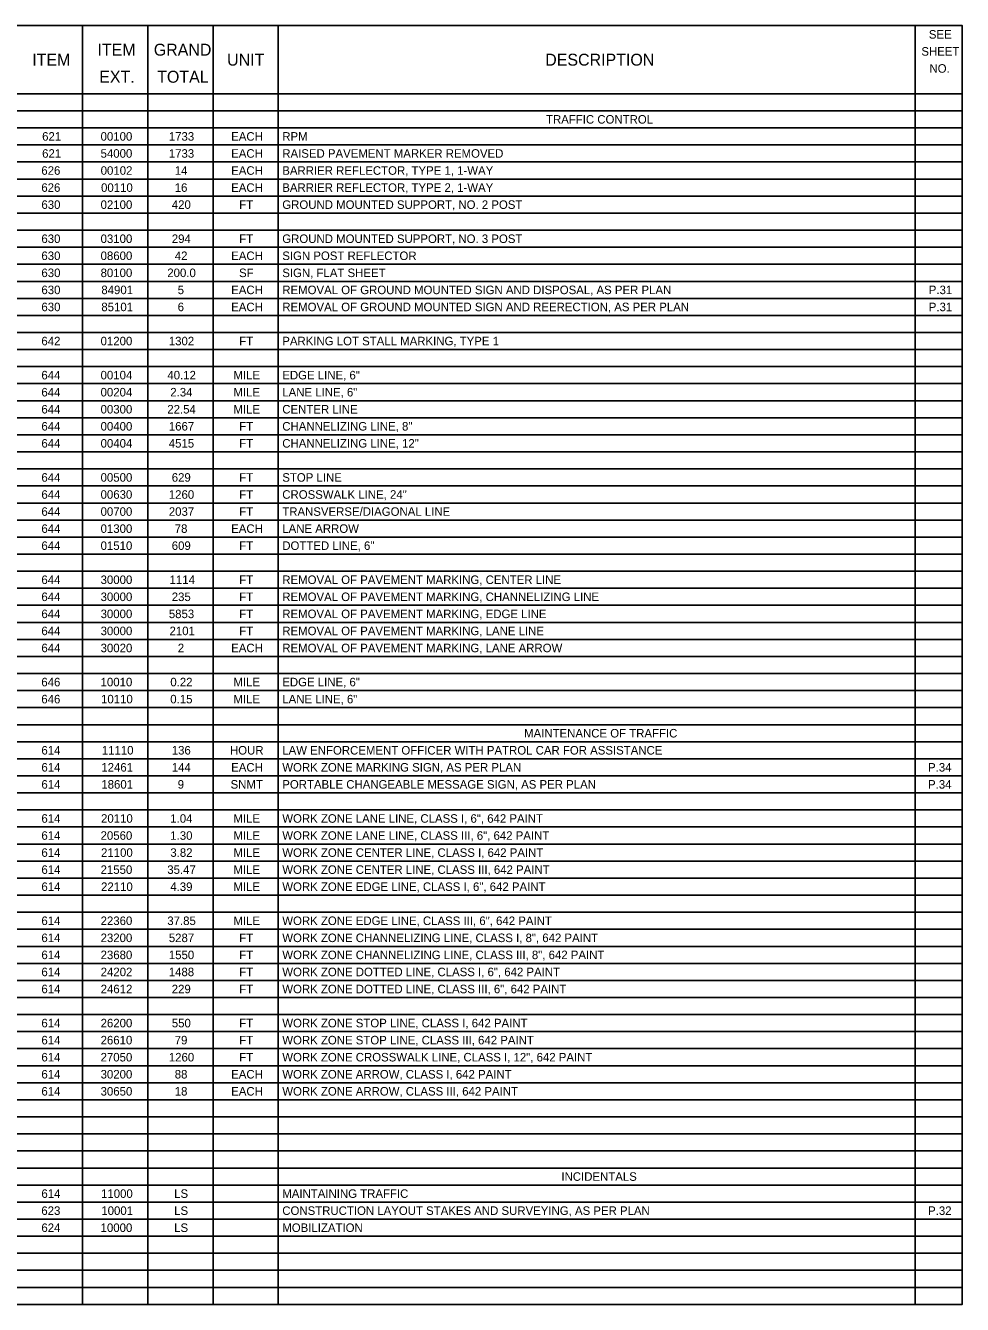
# Model space of a CAD drawing. Extents: x 12522 to 13018, y 1124 to 1902.
# Drawn here: x 12736.42 to 12751.8, y 1804.65 to 1825.65 of the extents above; entities that cross this region are included whole.
import ezdxf

# ---------------------------------------------------------------- set-up
doc = ezdxf.new("R2010")
doc.units = 0
for name, color, linetype in [('SC_Scratch1', 7, 'Continuous'), ('SH_Data', 7, 'Continuous'), ('SH_Text', 7, 'Continuous')]:
    doc.layers.add(name, color=color, linetype=linetype)

msp = doc.modelspace()

# ---------------------------------------------------------------- linework, layer by layer
at = {"layer": 'SC_Scratch1'}
msp.add_lwpolyline([(12721.301, 1825.65), (12751.801, 1825.65), (12751.801, 1804.65), (12721.301, 1804.65)], close=True, dxfattribs=at)
at = {"layer": 'SH_Data'}
for p, q in [((12737.359, 1825.65), (12737.359, 1804.65)), ((12738.43, 1825.65), (12738.43, 1804.65)), ((12739.501, 1825.65), (12739.501, 1804.65)), ((12740.571, 1825.65), (12740.571, 1804.65)), ((12751.03, 1825.65), (12751.03, 1804.65)), ((12721.301, 1824.53), (12751.804, 1824.53)), ((12721.301, 1824.25), (12751.804, 1824.25)), ((12721.301, 1823.97), (12751.804, 1823.97)), ((12721.301, 1823.69), (12751.804, 1823.69)), ((12721.301, 1823.41), (12751.804, 1823.41)), ((12721.301, 1823.13), (12751.804, 1823.13)), ((12721.301, 1822.85), (12751.804, 1822.85)), ((12721.301, 1822.57), (12751.804, 1822.57)), ((12721.301, 1822.29), (12751.804, 1822.29)), ((12721.301, 1822.01), (12751.804, 1822.01)), ((12721.301, 1821.73), (12751.804, 1821.73)), ((12721.301, 1821.45), (12751.804, 1821.45)), ((12721.301, 1821.17), (12751.804, 1821.17)), ((12721.301, 1820.89), (12751.804, 1820.89)), ((12721.301, 1820.61), (12751.804, 1820.61)), ((12721.301, 1820.33), (12751.804, 1820.33)), ((12721.301, 1820.05), (12751.804, 1820.05)), ((12721.301, 1819.77), (12751.804, 1819.77)), ((12721.301, 1819.49), (12751.804, 1819.49)), ((12721.301, 1819.21), (12751.804, 1819.21)), ((12721.301, 1818.93), (12751.804, 1818.93)), ((12721.301, 1818.65), (12751.804, 1818.65)), ((12721.301, 1818.37), (12751.804, 1818.37)), ((12721.301, 1818.09), (12751.804, 1818.09)), ((12721.301, 1817.81), (12751.804, 1817.81)), ((12721.301, 1817.53), (12751.804, 1817.53)), ((12721.301, 1817.25), (12751.804, 1817.25)), ((12721.301, 1816.97), (12751.804, 1816.97)), ((12721.301, 1816.69), (12751.804, 1816.69)), ((12721.301, 1816.41), (12751.804, 1816.41)), ((12721.301, 1816.13), (12751.804, 1816.13)), ((12721.301, 1815.85), (12751.804, 1815.85)), ((12721.301, 1815.57), (12751.804, 1815.57)), ((12721.301, 1815.29), (12751.804, 1815.29)), ((12721.301, 1815.01), (12751.804, 1815.01)), ((12721.301, 1814.73), (12751.804, 1814.73)), ((12721.301, 1814.45), (12751.804, 1814.45)), ((12721.301, 1814.17), (12751.804, 1814.17)), ((12721.301, 1813.89), (12751.804, 1813.89)), ((12721.301, 1813.61), (12751.804, 1813.61)), ((12721.301, 1813.33), (12751.804, 1813.33)), ((12721.301, 1813.05), (12751.804, 1813.05)), ((12721.301, 1812.77), (12751.804, 1812.77)), ((12721.301, 1812.49), (12751.804, 1812.49)), ((12721.301, 1812.21), (12751.804, 1812.21)), ((12721.301, 1811.93), (12751.804, 1811.93)), ((12721.301, 1811.65), (12751.804, 1811.65)), ((12721.301, 1811.37), (12751.804, 1811.37)), ((12721.301, 1811.09), (12751.804, 1811.09)), ((12721.301, 1810.81), (12751.804, 1810.81)), ((12721.301, 1810.53), (12751.804, 1810.53)), ((12721.301, 1810.25), (12751.804, 1810.25)), ((12721.301, 1809.97), (12751.804, 1809.97)), ((12721.301, 1809.69), (12751.804, 1809.69)), ((12721.301, 1809.41), (12751.804, 1809.41)), ((12721.301, 1809.13), (12751.804, 1809.13)), ((12721.301, 1808.85), (12751.804, 1808.85)), ((12721.301, 1808.57), (12751.804, 1808.57)), ((12721.301, 1808.29), (12751.804, 1808.29)), ((12721.301, 1808.01), (12751.804, 1808.01)), ((12721.301, 1807.73), (12751.804, 1807.73)), ((12721.301, 1807.45), (12751.804, 1807.45)), ((12721.301, 1807.17), (12751.804, 1807.17)), ((12721.301, 1806.89), (12751.804, 1806.89)), ((12721.301, 1806.61), (12751.804, 1806.61)), ((12721.301, 1806.33), (12751.804, 1806.33)), ((12721.301, 1806.05), (12751.804, 1806.05)), ((12721.301, 1805.77), (12751.804, 1805.77)), ((12721.301, 1805.49), (12751.804, 1805.49)), ((12721.301, 1805.21), (12751.804, 1805.21)), ((12721.301, 1804.93), (12751.804, 1804.93))]:
    msp.add_line(p, q, dxfattribs=at)

# ---------------------------------------------------------------- texts
at = {"layer": 'SH_Text'}
for s, height, p in [('SEE', 0.14, (12751.253, 1825.436)), ('ITEM', 0.196, (12737.602, 1825.156)), ('GRAND', 0.196, (12738.527, 1825.156)), ('ITEM', 0.196, (12736.531, 1824.992)), ('UNIT', 0.196, (12739.731, 1824.992)), ('DESCRIPTION', 0.196, (12744.954, 1824.992)), ('SHEET', 0.14, (12751.13, 1825.156)), ('EXT.', 0.196, (12737.631, 1824.712)), ('TOTAL', 0.196, (12738.583, 1824.712)), ('NO.', 0.14, (12751.263, 1824.876)), ('TRAFFIC CONTROL', 0.14, (12744.967, 1824.04)), ('621', 0.14, (12736.694, 1823.76)), ('00100', 0.14, (12737.654, 1823.76)), ('1733', 0.14, (12738.774, 1823.76)), ('EACH', 0.14, (12739.798, 1823.76)), ('RPM', 0.14, (12740.637, 1823.76)), ('621', 0.14, (12736.694, 1823.48)), ('54000', 0.14, (12737.654, 1823.48)), ('1733', 0.14, (12738.774, 1823.48)), ('EACH', 0.14, (12739.798, 1823.48)), ('RAISED PAVEMENT MARKER REMOVED', 0.14, (12740.637, 1823.48)), ('626', 0.14, (12736.681, 1823.2)), ('00102', 0.14, (12737.655, 1823.2)), ('14', 0.14, (12738.872, 1823.2)), ('EACH', 0.14, (12739.798, 1823.2)), ('BARRIER REFLECTOR, TYPE 1, 1-WAY', 0.14, (12740.637, 1823.2)), ('626', 0.14, (12736.681, 1822.92)), ('00110', 0.14, (12737.661, 1822.92)), ('16', 0.14, (12738.871, 1822.92)), ('EACH', 0.14, (12739.798, 1822.92)), ('BARRIER REFLECTOR, TYPE 2, 1-WAY', 0.14, (12740.637, 1822.92)), ('630', 0.14, (12736.682, 1822.64)), ('02100', 0.14, (12737.654, 1822.64)), ('420', 0.14, (12738.823, 1822.64)), ('FT', 0.14, (12739.93, 1822.64)), ('GROUND MOUNTED SUPPORT, NO. 2 POST', 0.14, (12740.637, 1822.64)), ('630', 0.14, (12736.682, 1822.08)), ('03100', 0.14, (12737.654, 1822.08)), ('294', 0.14, (12738.823, 1822.08)), ('FT', 0.14, (12739.93, 1822.08)), ('GROUND MOUNTED SUPPORT, NO. 3 POST', 0.14, (12740.637, 1822.08)), ('630', 0.14, (12736.682, 1821.8)), ('08600', 0.14, (12737.654, 1821.8)), ('42', 0.14, (12738.872, 1821.8)), ('EACH', 0.14, (12739.798, 1821.8)), ('SIGN POST REFLECTOR', 0.14, (12740.637, 1821.8)), ('630', 0.14, (12736.682, 1821.52)), ('80100', 0.14, (12737.654, 1821.52)), ('200.0', 0.14, (12738.749, 1821.52)), ('SF', 0.14, (12739.927, 1821.52)), ('SIGN, FLAT SHEET', 0.14, (12740.637, 1821.52)), ('630', 0.14, (12736.682, 1821.24)), ('84901', 0.14, (12737.666, 1821.24)), ('5', 0.14, (12738.92, 1821.24)), ('EACH', 0.14, (12739.798, 1821.24)), ('REMOVAL OF GROUND MOUNTED SIGN AND DISPOSAL, AS PER PLAN', 0.14, (12740.637, 1821.24)), ('P.31', 0.14, (12751.252, 1821.24)), ('630', 0.14, (12736.682, 1820.96)), ('85101', 0.14, (12737.666, 1820.96)), ('6', 0.14, (12738.92, 1820.96)), ('EACH', 0.14, (12739.798, 1820.96)), ('REMOVAL OF GROUND MOUNTED SIGN AND REERECTION, AS PER PLAN', 0.14, (12740.637, 1820.96)), ('P.31', 0.14, (12751.252, 1820.96)), ('642', 0.14, (12736.682, 1820.4)), ('01200', 0.14, (12737.654, 1820.4)), ('1302', 0.14, (12738.774, 1820.4)), ('FT', 0.14, (12739.93, 1820.4)), ('PARKING LOT STALL MARKING, TYPE 1', 0.14, (12740.637, 1820.4)), ('644', 0.14, (12736.682, 1819.84)), ('00104', 0.14, (12737.654, 1819.84)), ('40.12', 0.14, (12738.75, 1819.84)), ('MILE', 0.14, (12739.835, 1819.84)), ('EDGE LINE, 6"', 0.14, (12740.637, 1819.84)), ('644', 0.14, (12736.682, 1819.56)), ('00204', 0.14, (12737.654, 1819.56)), ('2.34', 0.14, (12738.798, 1819.56)), ('MILE', 0.14, (12739.835, 1819.56)), ('LANE LINE, 6"', 0.14, (12740.637, 1819.56)), ('644', 0.14, (12736.682, 1819.28)), ('00300', 0.14, (12737.654, 1819.28)), ('22.54', 0.14, (12738.749, 1819.28)), ('MILE', 0.14, (12739.835, 1819.28)), ('CENTER LINE', 0.14, (12740.637, 1819.28)), ('644', 0.14, (12736.682, 1819)), ('00400', 0.14, (12737.654, 1819)), ('1667', 0.14, (12738.774, 1819)), ('FT', 0.14, (12739.93, 1819)), ('CHANNELIZING LINE, 8"', 0.14, (12740.637, 1819)), ('644', 0.14, (12736.682, 1818.72)), ('00404', 0.14, (12737.654, 1818.72)), ('4515', 0.14, (12738.773, 1818.72)), ('FT', 0.14, (12739.93, 1818.72)), ('CHANNELIZING LINE, 12"', 0.14, (12740.637, 1818.72)), ('644', 0.14, (12736.682, 1818.16)), ('00500', 0.14, (12737.654, 1818.16)), ('629', 0.14, (12738.822, 1818.16)), ('FT', 0.14, (12739.93, 1818.16)), ('STOP LINE', 0.14, (12740.637, 1818.16)), ('644', 0.14, (12736.682, 1817.88)), ('00630', 0.14, (12737.654, 1817.88)), ('1260', 0.14, (12738.774, 1817.88)), ('FT', 0.14, (12739.93, 1817.88)), ('CROSSWALK LINE, 24"', 0.14, (12740.637, 1817.88)), ('644', 0.14, (12736.682, 1817.6)), ('00700', 0.14, (12737.654, 1817.6)), ('2037', 0.14, (12738.774, 1817.6)), ('FT', 0.14, (12739.93, 1817.6)), ('TRANSVERSE/DIAGONAL LINE', 0.14, (12740.637, 1817.6)), ('644', 0.14, (12736.682, 1817.32)), ('01300', 0.14, (12737.654, 1817.32)), ('78', 0.14, (12738.871, 1817.32)), ('EACH', 0.14, (12739.798, 1817.32)), ('LANE ARROW', 0.14, (12740.637, 1817.32)), ('644', 0.14, (12736.682, 1817.04)), ('01510', 0.14, (12737.654, 1817.04)), ('609', 0.14, (12738.822, 1817.04)), ('FT', 0.14, (12739.93, 1817.04)), ('DOTTED LINE, 6"', 0.14, (12740.637, 1817.04)), ('644', 0.14, (12736.682, 1816.48)), ('30000', 0.14, (12737.654, 1816.48)), ('1114', 0.14, (12738.787, 1816.48)), ('FT', 0.14, (12739.93, 1816.48)), ('REMOVAL OF PAVEMENT MARKING, CENTER LINE', 0.14, (12740.637, 1816.48)), ('644', 0.14, (12736.682, 1816.2)), ('30000', 0.14, (12737.654, 1816.2)), ('235', 0.14, (12738.822, 1816.2)), ('FT', 0.14, (12739.93, 1816.2)), ('REMOVAL OF PAVEMENT MARKING, CHANNELIZING LINE', 0.14, (12740.637, 1816.2)), ('644', 0.14, (12736.682, 1815.92)), ('30000', 0.14, (12737.654, 1815.92)), ('5853', 0.14, (12738.774, 1815.92)), ('FT', 0.14, (12739.93, 1815.92)), ('REMOVAL OF PAVEMENT MARKING, EDGE LINE', 0.14, (12740.637, 1815.92)), ('644', 0.14, (12736.682, 1815.64)), ('30000', 0.14, (12737.654, 1815.64)), ('2101', 0.14, (12738.786, 1815.64)), ('FT', 0.14, (12739.93, 1815.64)), ('REMOVAL OF PAVEMENT MARKING, LANE LINE', 0.14, (12740.637, 1815.64)), ('644', 0.14, (12736.682, 1815.36)), ('30020', 0.14, (12737.654, 1815.36)), ('2', 0.14, (12738.921, 1815.36)), ('EACH', 0.14, (12739.798, 1815.36)), ('REMOVAL OF PAVEMENT MARKING, LANE ARROW', 0.14, (12740.637, 1815.36)), ('646', 0.14, (12736.681, 1814.8)), ('10010', 0.14, (12737.654, 1814.8)), ('0.22', 0.14, (12738.799, 1814.8)), ('MILE', 0.14, (12739.835, 1814.8)), ('EDGE LINE, 6"', 0.14, (12740.637, 1814.8)), ('646', 0.14, (12736.681, 1814.52)), ('10110', 0.14, (12737.661, 1814.52)), ('0.15', 0.14, (12738.798, 1814.52)), ('MILE', 0.14, (12739.835, 1814.52)), ('LANE LINE, 6"', 0.14, (12740.637, 1814.52)), ('MAINTENANCE OF TRAFFIC', 0.14, (12744.607, 1813.96)), ('614', 0.14, (12736.682, 1813.68)), ('11110', 0.14, (12737.674, 1813.68)), ('136', 0.14, (12738.822, 1813.68)), ('HOUR', 0.14, (12739.778, 1813.68)), ('LAW ENFORCEMENT OFFICER WITH PATROL CAR FOR ASSISTANCE', 0.14, (12740.637, 1813.68)), ('614', 0.14, (12736.682, 1813.4)), ('12461', 0.14, (12737.666, 1813.4)), ('144', 0.14, (12738.823, 1813.4)), ('EACH', 0.14, (12739.798, 1813.4)), ('WORK ZONE MARKING SIGN, AS PER PLAN', 0.14, (12740.637, 1813.4)), ('P.34', 0.14, (12751.24, 1813.4)), ('614', 0.14, (12736.682, 1813.12)), ('18601', 0.14, (12737.666, 1813.12)), ('9', 0.14, (12738.92, 1813.12)), ('SNMT', 0.14, (12739.788, 1813.12)), ('PORTABLE CHANGEABLE MESSAGE SIGN, AS PER PLAN', 0.14, (12740.637, 1813.12)), ('P.34', 0.14, (12751.24, 1813.12)), ('614', 0.14, (12736.682, 1812.56)), ('20110', 0.14, (12737.661, 1812.56)), ('1.04', 0.14, (12738.798, 1812.56)), ('MILE', 0.14, (12739.835, 1812.56)), ('WORK ZONE LANE LINE, CLASS I, 6", 642 PAINT', 0.14, (12740.637, 1812.56)), ('614', 0.14, (12736.682, 1812.28)), ('20560', 0.14, (12737.654, 1812.28)), ('1.30', 0.14, (12738.798, 1812.28)), ('MILE', 0.14, (12739.835, 1812.28)), ('WORK ZONE LANE LINE, CLASS III, 6", 642 PAINT', 0.14, (12740.637, 1812.28)), ('614', 0.14, (12736.682, 1812)), ('21100', 0.14, (12737.661, 1812)), ('3.82', 0.14, (12738.799, 1812)), ('MILE', 0.14, (12739.835, 1812)), ('WORK ZONE CENTER LINE, CLASS I, 642 PAINT', 0.14, (12740.637, 1812)), ('614', 0.14, (12736.682, 1811.72)), ('21550', 0.14, (12737.654, 1811.72)), ('35.47', 0.14, (12738.749, 1811.72)), ('MILE', 0.14, (12739.835, 1811.72)), ('WORK ZONE CENTER LINE, CLASS III, 642 PAINT', 0.14, (12740.637, 1811.72)), ('614', 0.14, (12736.682, 1811.44)), ('22110', 0.14, (12737.661, 1811.44)), ('4.39', 0.14, (12738.798, 1811.44)), ('MILE', 0.14, (12739.835, 1811.44)), ('WORK ZONE EDGE LINE, CLASS I, 6", 642 PAINT', 0.14, (12740.637, 1811.44)), ('614', 0.14, (12736.682, 1810.88)), ('22360', 0.14, (12737.654, 1810.88)), ('37.85', 0.14, (12738.749, 1810.88)), ('MILE', 0.14, (12739.835, 1810.88)), ('WORK ZONE EDGE LINE, CLASS III, 6", 642 PAINT', 0.14, (12740.637, 1810.88)), ('614', 0.14, (12736.682, 1810.6)), ('23200', 0.14, (12737.654, 1810.6)), ('5287', 0.14, (12738.774, 1810.6)), ('FT', 0.14, (12739.93, 1810.6)), ('WORK ZONE CHANNELIZING LINE, CLASS I, 8", 642 PAINT', 0.14, (12740.637, 1810.6)), ('614', 0.14, (12736.682, 1810.32)), ('23680', 0.14, (12737.654, 1810.32)), ('1550', 0.14, (12738.774, 1810.32)), ('FT', 0.14, (12739.93, 1810.32)), ('WORK ZONE CHANNELIZING LINE, CLASS III, 8", 642 PAINT', 0.14, (12740.637, 1810.32)), ('614', 0.14, (12736.682, 1810.04)), ('24202', 0.14, (12737.655, 1810.04)), ('1488', 0.14, (12738.773, 1810.04)), ('FT', 0.14, (12739.93, 1810.04)), ('WORK ZONE DOTTED LINE, CLASS I, 6", 642 PAINT', 0.14, (12740.637, 1810.04)), ('614', 0.14, (12736.682, 1809.76)), ('24612', 0.14, (12737.655, 1809.76)), ('229', 0.14, (12738.822, 1809.76)), ('FT', 0.14, (12739.93, 1809.76)), ('WORK ZONE DOTTED LINE, CLASS III, 6", 642 PAINT', 0.14, (12740.637, 1809.76)), ('614', 0.14, (12736.682, 1809.2)), ('26200', 0.14, (12737.654, 1809.2)), ('550', 0.14, (12738.823, 1809.2)), ('FT', 0.14, (12739.93, 1809.2)), ('WORK ZONE STOP LINE, CLASS I, 642 PAINT', 0.14, (12740.637, 1809.2)), ('614', 0.14, (12736.682, 1808.92)), ('26610', 0.14, (12737.654, 1808.92)), ('79', 0.14, (12738.871, 1808.92)), ('FT', 0.14, (12739.93, 1808.92)), ('WORK ZONE STOP LINE, CLASS III, 642 PAINT', 0.14, (12740.637, 1808.92)), ('614', 0.14, (12736.682, 1808.64)), ('27050', 0.14, (12737.654, 1808.64)), ('1260', 0.14, (12738.774, 1808.64)), ('FT', 0.14, (12739.93, 1808.64)), ('WORK ZONE CROSSWALK LINE, CLASS I, 12", 642 PAINT', 0.14, (12740.637, 1808.64)), ('614', 0.14, (12736.682, 1808.36)), ('30200', 0.14, (12737.654, 1808.36)), ('88', 0.14, (12738.871, 1808.36)), ('EACH', 0.14, (12739.798, 1808.36)), ('WORK ZONE ARROW, CLASS I, 642 PAINT', 0.14, (12740.637, 1808.36)), ('614', 0.14, (12736.682, 1808.08)), ('30650', 0.14, (12737.654, 1808.08)), ('18', 0.14, (12738.871, 1808.08)), ('EACH', 0.14, (12739.798, 1808.08)), ('WORK ZONE ARROW, CLASS III, 642 PAINT', 0.14, (12740.637, 1808.08)), ('INCIDENTALS', 0.14, (12745.22, 1806.68)), ('614', 0.14, (12736.682, 1806.4)), ('11000', 0.14, (12737.661, 1806.4)), ('LS', 0.14, (12738.862, 1806.4)), ('MAINTAINING TRAFFIC', 0.14, (12740.637, 1806.4)), ('623', 0.14, (12736.681, 1806.12)), ('10001', 0.14, (12737.666, 1806.12)), ('LS', 0.14, (12738.862, 1806.12)), ('CONSTRUCTION LAYOUT STAKES AND SURVEYING, AS PER PLAN', 0.14, (12740.637, 1806.12)), ('P.32', 0.14, (12751.241, 1806.12)), ('624', 0.14, (12736.682, 1805.84)), ('10000', 0.14, (12737.654, 1805.84)), ('LS', 0.14, (12738.862, 1805.84)), ('MOBILIZATION', 0.14, (12740.637, 1805.84))]:
    msp.add_text(s, height=height, dxfattribs=at).set_placement(p)

doc.saveas('drawing.dxf')
